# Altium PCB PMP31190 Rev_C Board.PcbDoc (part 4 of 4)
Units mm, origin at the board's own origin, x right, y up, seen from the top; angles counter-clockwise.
Board outline 175.26 x 91.44 mm, 4 copper layers (Top Layer, Mid-Layer 1, Mid-Layer 2, Bottom Layer), stack 1.473 mm thick; 252 components, 140 nets, 735 pads, 501 vias.
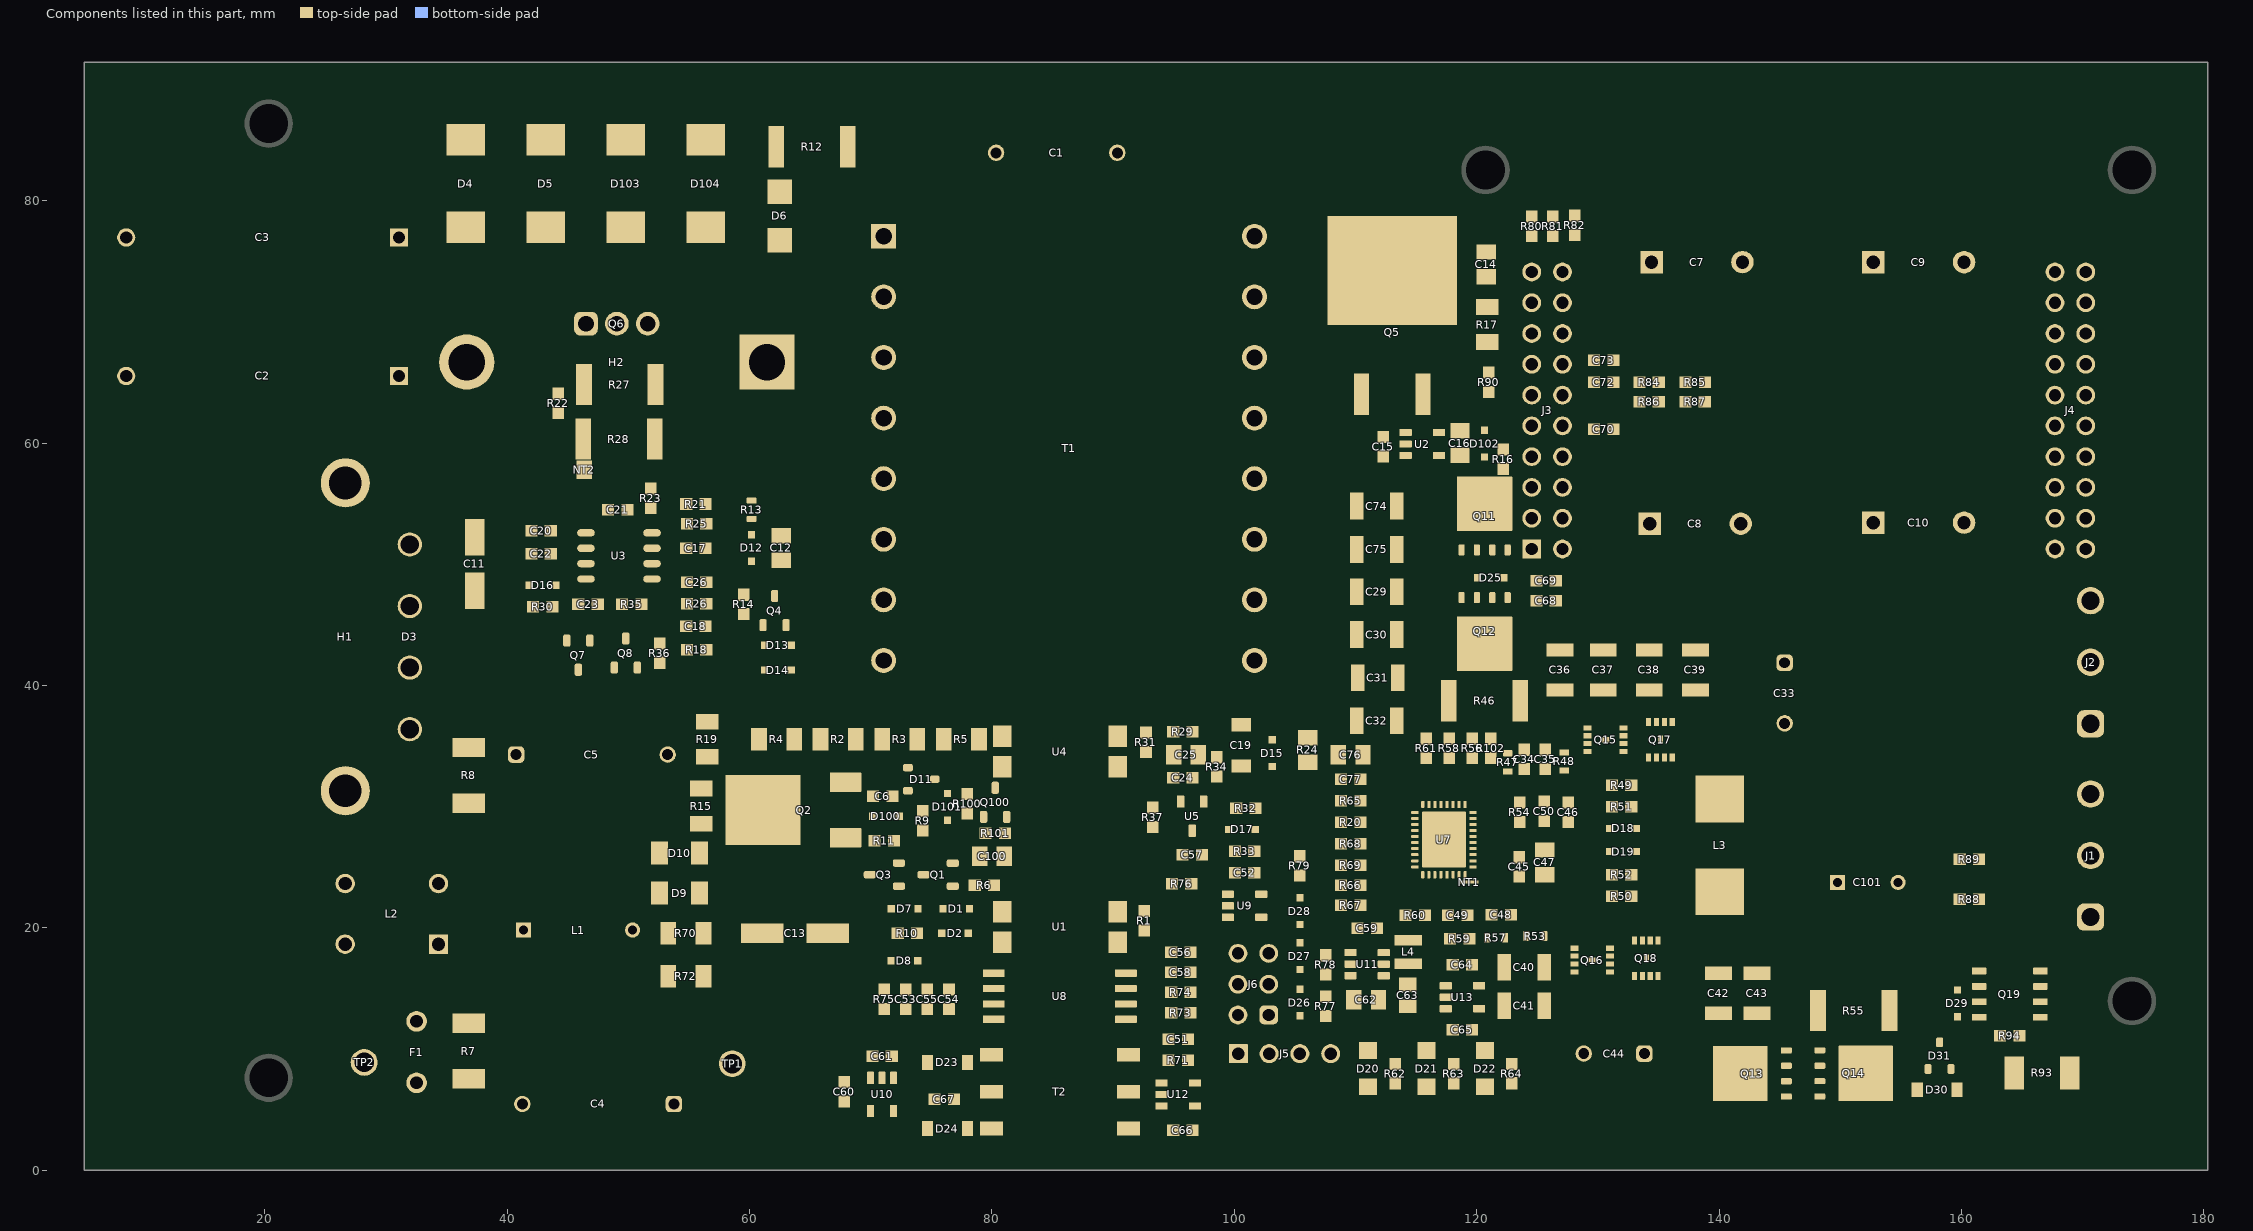
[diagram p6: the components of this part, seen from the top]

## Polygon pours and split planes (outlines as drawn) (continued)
NetD103_1 on Top Layer "TOP_LAYER_NETD103_1_P134" (solid, remove dead copper, pour order 134): 46.863,83.947 48.133,82.677 59.563,82.677 60.452,83.566 60.452,88.011 58.928,89.535 48.133,89.535 46.863,88.265
NetD5_1 on Top Layer "TOP_LAYER_NETD5_1_P130" (solid, remove dead copper, pour order 130): 41.106,80.01 51.435,80.01 52.324,79.121 52.324,73.279 51.435,72.39 45.466,72.39 44.069,70.993 41.275,70.993 40.259,72.009 40.259,79.375
NetD4_1 on Top Layer "TOP_LAYER_NETD4_1_P127" (solid, remove dead copper, pour order 127): 44.831,82.931 45.847,83.947 45.847,88.392 44.831,89.408 25.654,89.408 24.892,88.646 24.892,83.82 25.781,82.931
AGND on Top Layer "TOP_LAYER_AGND_P119" (solid, pour order 119): 106.426,35.433 114.681,35.433 115.316,36.068 125.349,36.068 126.111,35.306 126.111,32.004 125.857,31.75 123.317,31.75 121.793,30.226 116.205,30.226 115.57,29.591 116.332,28.829 116.332,24.638 116.967,24.003 121.336,24.003 122.225,23.114 122.936,23.114 123.571,22.479 125.73,22.479 125.857,22.352 125.857,20.447 125.349,19.939 107.442,19.939 106.426,20.955
NetJ2_1 on Top Layer "TOP_LAYER_NETJ2_1_P091" (solid, pour order 91): 165.695,16.978 166.243,17.526 169.164,17.526 169.926,16.764 169.926,12.065 169.418,11.557 166.37,11.557 165.695,12.232
SGND on Top Layer "TOP_LAYER_SGND_P121" (solid, pour order 121): 104.775,57.785 121.92,57.785 123.19,59.055 123.19,77.47 129.54,83.82 165.1,83.82 176.53,72.39 176.53,22.225 173.355,19.05 170.18,19.05 168.275,17.145 168.275,10.16 160.528,2.413 92.837,2.413 89.535,5.715 89.535,54.61 92.71,57.785
BAT on Top Layer "TOP_LAYER_BAT_P089" (solid, pour order 89): 153.162,14.986 153.924,15.748 158.75,15.748 160.655,17.653 163.195,17.653 163.83,17.018 163.83,13.335 163.576,13.081 159.385,13.081 157.734,11.43 153.416,11.43 153.162,11.684
BAT_SRC on Top Layer "TOP_LAYER_BAT_SRC_P077" (solid, pour order 77): 144.907,9.144 146.558,9.144 147.955,10.541 149.098,10.541 149.225,10.414 149.225,5.715 148.844,5.334 145.161,5.334 144.653,5.842 144.653,9.017
NetC40_1 on Top Layer "TOP_LAYER_NETC40_1_P112" (solid, pour order 112): 138.43,13.589 139.446,14.605 144.526,14.605 145.288,15.367 149.225,15.367 149.86,14.732 149.86,11.303 149.733,11.176 144.78,11.176 144.399,10.795 144.399,5.461 144.018,5.08 131.953,5.08 130.683,6.35 130.683,10.287 129.794,11.176 124.333,11.176 123.952,11.557 123.952,18.034 124.333,18.415 126.238,18.415 127.254,19.431 130.175,19.431 130.429,19.177 130.429,14.859 132.588,12.7 137.541,12.7
NetC45_1 on Top Layer "TOP_LAYER_NETC45_1_P092" (solid, pour order 92): 136.144,25.527 136.652,26.035 141.986,26.035 142.621,25.4 142.621,20.574 141.605,19.558 137.033,19.558 136.398,18.923 136.398,17.272 136.017,16.891 132.461,16.891 131.699,16.129 130.556,16.129 130.556,17.907 131.445,17.907 131.699,18.161 131.699,20.193 132.715,21.209 134.366,21.209 136.144,22.987
NetC46_1 on Top Layer "TOP_LAYER_NETC46_1_P079" (solid, pour order 79): 131.572,36.068 131.826,36.322 139.319,36.322 142.621,33.02 142.621,28.321 142.113,27.813 136.779,27.813 136.144,28.448 136.144,32.639 135.509,33.274 131.826,33.274 131.572,33.528
SYSTEM on Top Layer "TOP_LAYER_SYSTEM_P082" (solid, pour order 82): 122.174,39.751 122.682,40.259 123.571,40.259 124.206,40.894 140.716,40.894 143.383,43.561 145.923,43.561 147.066,42.418 147.066,39.497 146.431,38.862 143.637,38.862 131.699,38.862 131.191,38.354 131.191,34.036 131.064,33.909 126.492,33.909 126.365,34.036 126.365,35.306 125.73,35.941 122.428,35.941 122.174,36.195 122.174,36.322
SGND on Top Layer "TOP_LAYER_SGND_P123" (solid, pour order 123): 120.015,75.184 119.634,75.565 119.634,78.613 119.888,78.867 121.539,78.867 121.793,78.613 121.793,75.184
NetQ12_5 on Top Layer "TOP_LAYER_NETQ12_5_P075" (solid, pour order 75): 123.317,46.101 123.571,45.847 123.571,41.021 123.19,40.64 122.047,40.64 121.92,40.513 121.92,36.957 121.158,36.195 116.84,36.195 116.713,36.322 116.713,40.64 117.729,41.656 117.729,45.593 118.237,46.101 118.491,46.101 118.237,46.101 118.491,46.101
NetD25_2 on Top Layer "TOP_LAYER_NETD25_2_P071" (solid, pour order 71): 118.11,51.689 121.666,51.689 121.793,51.562 121.793,50.165 121.412,49.784 121.412,48.387 121.666,48.133 122.809,48.133 123.063,47.879 123.063,46.609 118.237,46.609 118.11,46.736
+24V on Top Layer "TOP_LAYER_+24V_P076" (solid, pour order 76): 112.395,36.195 111.506,35.306 109.982,35.306 109.728,35.052 109.728,31.877 109.855,31.75 111.252,31.75 112.522,33.02 112.522,33.782 116.205,37.465 116.205,40.64 117.475,41.91 117.475,51.435 118.11,52.07 123.19,52.07 123.19,56.515 121.92,57.785 113.03,57.785 113.03,56.515 112.395,55.88
+24V on Top Layer "TOP_LAYER_+24V_P120" (solid, pour order 120): 147.828,41.656 149.352,40.132 155.702,40.132 156.845,41.275 156.845,79.375 154.94,81.28 133.35,81.28 131.445,79.375 131.445,72.39 135.255,68.58 137.795,68.58 140.335,66.04 140.335,62.23 137.795,59.69 133.985,59.69 132.08,57.785 132.08,48.26 135.255,45.085 145.796,45.085 147.828,43.053
SGND on Top Layer "TOP_LAYER_SGND_P118" (solid, pour order 118): 112.014,66.802 119.38,66.802 119.38,63.5 118.999,63.119 117.983,62.103 117.983,61.722 117.729,61.468 114.935,61.468 113.792,62.611 112.014,62.611
NetQ5_4 on Top Layer "TOP_LAYER_NETQ5_4_P117" (solid, pour order 117): 97.155,83.82 114.3,83.82 115.57,82.55 115.57,80.645 116.84,79.375 118.11,79.375 118.745,78.74 118.745,67.945 118.11,67.31 108.585,67.31 107.315,66.04 107.315,60.325 106.68,59.69 98.425,59.69 97.155,60.96
PGND on Top Layer "TOP_LAYER_PGND_P116" (solid, pour order 116): 45.72,66.675 49.53,66.675 49.53,57.785 45.72,57.785
CGND on Top Layer "TOP_LAYER_CGND_P115" (solid, pour order 115): 81.534,39.751 81.534,6.223 77.724,2.413 66.675,2.413 64.77,4.318 64.77,11.43 60.325,15.875 60.325,38.735 41.275,38.735 34.925,45.085 34.925,55.88 36.83,57.785 64.77,57.785 66.675,55.88 66.675,51.435 69.215,48.895 72.39,48.895
NetQ6_2 on Top Layer "TOP_LAYER_NETQ6_2_P113" (solid, pour order 113): 63.754,71.755 63.754,84.582 65.532,86.36 69.088,86.36 69.088,71.755
NetQ6_3 on Top Layer "TOP_LAYER_NETQ6_3_P111" (solid, pour order 111): 50.165,71.12 50.8,71.755 52.705,71.755 53.975,70.485 53.975,59.055 53.34,58.42 50.165,58.42 50.165,67.31
NetC2_1 on Top Layer "TOP_LAYER_NETC2_1_P101" (solid, pour order 101): 38.989,79.248 38.227,80.01 25.781,80.01 24.765,78.994 24.765,72.136 25.781,71.12 38.227,71.12 38.989,71.882
NetD3_3 on Top Layer "TOP_LAYER_NETD3_3_P094" (solid, pour order 94): 35.38,34.11 35.38,37.26 38.28,37.26 38.28,34.11
NetF1_1 on Top Layer "TOP_LAYER_NETF1_1_P083" (solid, pour order 83): 24.295,20.36 24.75,20.815 27.905,20.815 29.08,19.64 29.21,19.64 30.52,18.33 30.52,15.61 32.137,13.993 33.355,13.993 33.909,13.439 33.909,10.932 33.307,10.33 32.862,10.33 32.849,10.344 30.296,10.344 29.21,11.43 25.712,11.43 24.295,12.847
NetD6_1 on Mid-Layer 2 "MID-LAYER_2_NETD6_1_P135" (solid, remove dead copper, pour order 135): 53.467,79.121 53.467,71.755 54.864,70.358 61.595,70.358 63.5,72.263 63.5,77.978 62.357,79.121 61.214,79.121 60.198,80.137 54.483,80.137
NetD103_1 on Mid-Layer 2 "MID-LAYER_2_NETD103_1_P132" (solid, remove dead copper, pour order 132): 46.863,83.947 48.133,82.677 59.563,82.677 60.452,83.566 60.452,88.011 58.928,89.535 48.133,89.535 46.863,88.265
NetD5_1 on Mid-Layer 2 "MID-LAYER_2_NETD5_1_P128" (solid, remove dead copper, pour order 128): 41.106,80.01 51.435,80.01 52.324,79.121 52.324,73.279 51.435,72.39 45.466,72.39 44.069,70.993 41.275,70.993 40.259,72.009 40.259,79.375
NetC2_1 on Mid-Layer 2 "MID-LAYER_2_NETC2_1_P125" (solid, pour order 125): 38.989,79.248 38.227,80.01 25.781,80.01 24.765,78.994 24.765,72.136 25.781,71.12 38.227,71.12 38.989,71.882
NetJ2_1 on Mid-Layer 2 "MID-LAYER_2_NETJ2_1_P122" (solid, pour order 122): 165.735,37.211 167.259,38.735 172.466,38.735 173.99,37.211 173.99,29.591 172.593,28.194 169.545,28.194 168.91,27.559 168.91,17.907 169.926,16.891 169.926,11.938 169.545,11.557 166.243,11.557 165.735,12.065 165.735,12.319
NetC45_1 on Mid-Layer 2 "MID-LAYER_2_NETC45_1_P074" (solid, pour order 74): 132.588,19.431 135.382,19.431 135.382,16.637 132.588,16.637
NetC40_1 on Mid-Layer 2 "MID-LAYER_2_NETC40_1_P073" (solid, pour order 73): 127.508,18.669 130.302,18.669 130.302,15.875 127.508,15.875
NetC46_1 on Mid-Layer 2 "MID-LAYER_2_NETC46_1_P072" (solid, pour order 72): 133.731,36.322 136.525,36.322 136.525,33.528 133.731,33.528
SYSTEM on Mid-Layer 2 "MID-LAYER_2_SYSTEM_P070" (solid, pour order 70): 128.397,36.957 131.191,36.957 131.191,34.163 128.397,34.163
NetQ5_4 on Mid-Layer 2 "MID-LAYER_2_NETQ5_4_P099" (solid, pour order 99): 97.155,83.82 114.3,83.82 115.57,82.55 115.57,80.645 116.84,79.375 118.11,79.375 118.745,78.74 118.745,67.945 118.11,67.31 108.585,67.31 107.315,66.04 107.315,60.325 106.68,59.69 98.425,59.69 97.155,60.96
NetC2_1 on Mid-Layer 2 "MID-LAYER_2_NETC2_1_P085" (solid, pour order 85): 33.409,49.859 30.182,49.859 29.389,50.652 29.389,60.781 28.295,61.874 27.795,61.874 27.795,77.91 29.895,80.01 34.29,80.01 34.29,75.557 33.655,74.922 33.655,71.12 32.385,69.85 32.385,66.04 33.509,64.916 33.509,50.049
NetD3_2 on Mid-Layer 2 "MID-LAYER_2_NETD3_2_P105" (solid, pour order 105): 29.865,48.09 30.606,48.831 35.23,48.831 52.07,31.991 52.07,19.05 51.435,18.415 48.26,18.415 46.355,20.32 46.355,33.081 42.401,37.035 41.195,37.035 33.509,44.721 30.52,44.721 29.874,45.367 29.865,45.359
NetC5_1 on Mid-Layer 2 "MID-LAYER_2_NETC5_1_P107" (solid, pour order 107): 32.93,22.225 32.975,22.225 33.542,21.658 35.402,21.658 39.28,17.78 39.375,17.685 42.45,17.685 43.815,19.05 43.815,20.955 42.545,22.225 40.257,22.225 38.86,23.622 38.86,26.602 43.165,30.907 43.165,34.619 42.099,35.685 40.065,35.685 39.49,35.11 39.49,30.69 32.93,24.13
NetD3_3 on Mid-Layer 2 "MID-LAYER_2_NETD3_3_P108" (solid, pour order 108): 25.13,22.225 24.495,22.86 24.495,26.348 25.003,26.856 28.106,26.856 34.33,33.08 34.33,37.795 32.755,39.37 30.5,39.37 29.865,40.005 29.865,42.998 30.52,43.653 33.167,43.653 38.28,38.54 38.28,31.182 38.154,31.182 28.63,21.658 25.697,21.658
SGND on Mid-Layer 1 "MID-LAYER_1_SGND_P138" (solid, remove dead copper, pour order 138): 89.662,55.245 89.662,85.09 91.313,86.741 94.361,86.741 95.631,85.471 95.631,55.245
NetD103_1 on Mid-Layer 1 "MID-LAYER_1_NETD103_1_P131" (solid, remove dead copper, pour order 131): 46.863,83.947 48.133,82.677 59.563,82.677 60.452,83.566 60.452,88.011 58.928,89.535 48.133,89.535 46.863,88.265
NetD4_1 on Mid-Layer 1 "MID-LAYER_1_NETD4_1_P126" (solid, remove dead copper, pour order 126): 44.831,82.931 45.847,83.947 45.847,88.392 44.831,89.408 25.654,89.408 24.892,88.646 24.892,83.82 25.781,82.931
NetC2_1 on Mid-Layer 1 "MID-LAYER_1_NETC2_1_P124" (solid, pour order 124): 38.989,79.248 38.227,80.01 25.781,80.01 24.765,78.994 24.765,72.136 25.781,71.12 38.227,71.12 38.989,71.882
AGND on Mid-Layer 1 "MID-LAYER_1_AGND_P109" (solid, pour order 109): 106.426,35.433 114.681,35.433 115.316,36.068 125.349,36.068 126.111,35.306 126.111,32.004 125.857,31.75 123.317,31.75 121.793,30.226 116.205,30.226 115.57,29.591 116.332,28.829 116.332,24.638 116.967,24.003 119.126,24.003 120.015,23.114 122.936,23.114 123.571,22.479 125.679,22.479 125.857,22.301 125.857,20.396 125.4,19.939 107.442,19.939 106.426,20.955
NetC45_1 on Mid-Layer 1 "MID-LAYER_1_NETC45_1_P078" (solid, pour order 78): 132.588,19.431 135.382,19.431 135.382,16.637 132.588,16.637
SGND on Mid-Layer 1 "MID-LAYER_1_SGND_P110" (solid, pour order 110): 89.662,6.223 93.345,2.54 169.545,2.54 176.53,9.525 176.53,78.74 175.895,79.375 171.45,79.375 169.545,81.28 169.545,83.82 168.91,84.455 125.095,84.455 124.46,83.82 124.46,80.645 122.555,78.74 120.65,78.74 120.015,78.105 120.015,67.31 119.507,66.802 109.347,66.802 108.585,66.04 108.585,59.69 107.315,58.42 90.17,58.42 89.662,57.912
NetC45_1 on Mid-Layer 1 "MID-LAYER_1_NETC45_1_P097" (solid, pour order 97): 132.588,19.558 135.382,19.558 135.382,16.764 132.588,16.764
NetC40_1 on Mid-Layer 1 "MID-LAYER_1_NETC40_1_P087" (solid, pour order 87): 127.508,18.796 130.302,18.796 130.302,16.002 127.508,16.002
NetC46_1 on Mid-Layer 1 "MID-LAYER_1_NETC46_1_P080" (solid, pour order 80): 133.731,36.322 136.525,36.322 136.525,33.528 133.731,33.528
SYSTEM on Mid-Layer 1 "MID-LAYER_1_SYSTEM_P084" (solid, pour order 84): 128.524,36.957 131.318,36.957 131.318,34.163 128.524,34.163
NetQ5_4 on Mid-Layer 1 "MID-LAYER_1_NETQ5_4_P106" (solid, pour order 106): 97.155,83.82 114.3,83.82 115.57,82.55 115.57,80.645 116.84,79.375 118.11,79.375 118.745,78.74 118.745,67.945 118.11,67.31 108.585,67.31 107.315,66.04 107.315,60.325 106.68,59.69 98.425,59.69 97.155,60.96
CGND on Mid-Layer 1 "MID-LAYER_1_CGND_P114" (solid, pour order 114): 66.675,55.88 66.675,51.435 69.215,48.895 72.39,48.895 81.534,39.751 81.534,6.223 77.724,2.413 66.802,2.413 64.77,4.445 64.77,11.43 60.325,15.875 60.325,38.672 41.338,38.672 34.989,45.021 34.989,55.245 34.925,55.88 36.83,57.785 49.022,57.785 49.022,57.721 64.834,57.721
NetC2_1 on Mid-Layer 1 "MID-LAYER_1_NETC2_1_P103" (solid, pour order 103): 65.405,69.85 64.77,70.485 56.515,70.485 54.61,72.39 40.005,72.39 38.735,71.12 28.575,71.12 27.94,71.755 27.94,78.105 31.115,81.28 71.755,81.28 74.295,78.74 74.295,71.12 73.025,69.85

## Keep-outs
Keep-Out Layer:
  text ".Layer_Name" at 14.275,-23.427 h1.52

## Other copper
Top Layer:
  text ".Layer_Name" at 14.275,-23.427 h1.52
Bottom Layer:
  text ".Layer_Name" at 14.275,-23.427 h1.52

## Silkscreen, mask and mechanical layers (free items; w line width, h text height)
Top Overlay:
  circle w0.254: c120.769,82.945 r3.582
  circle w0.254: c20.439,7.634 r3.582
  circle w0.254: c20.32,86.36 r3.582
  circle w0.254: c173.981,14.366 r3.582
  circle w0.254: c174.109,82.945 r3.582
  lines w0.254: 17.595,84.034 22.618,88.9 ; 17.714,5.308 22.737,10.174 ; 18.263,83.427 23.309,88.334 ; 18.382,4.701 23.428,9.608 ; 118.044,80.619 123.067,85.485 ; 118.712,80.012 123.758,84.919 ; 171.256,12.04 176.279,16.906 ; 171.384,80.619 176.407,85.485 ; 171.924,11.433 176.97,16.34 ; 172.052,80.012 177.098,84.919
  text "GND" at 178.054,45.974 h1.02 r90
  text "TS" at 177.927,41.275 h1.02 r90
  text "BATT+" at 178.054,34.29 h1.02 r90
  text "SYSTEM+" at 178.054,26.035 h1.02 r90
  text "GND" at 177.927,19.685 h1.02 r90
  text "'.PRJ_Number' .PCB_Rev" at 13.643,18.107 h2 r90
  text "LINE" at 26.416,5.715 h1.02
  text "NTRL" at 57.023,5.588 h1.02
  text ".Layer_Name" at 14.275,-23.427 h1.52
Bottom Overlay:
  lines w0.254: 118.186,11.42 118.186,36.82 cw(c122.801,36.82) 118.948,39.36 ccw(c115.096,41.9) 118.948,44.44 cw(c122.801,46.98) 118.186,46.98 118.186,85.08 176.606,85.08 176.606,46.98 cw(c171.992,46.98) 175.844,44.44 ccw(c179.697,41.9) 175.844,39.36 cw(c171.992,36.82) 176.606,36.82 176.606,11.42 169.875,11.42 cw(c169.875,16.035) 167.335,12.182 ccw(c164.795,8.33) 162.255,12.182 cw(c159.715,16.035) 159.715,11.42 133.807,11.42 133.807,12.436 132.461,12.436 132.461,13.96 131.521,13.96 131.521,12.436 127.711,12.436 127.711,13.96 126.771,13.96 126.771,12.436 125.425,12.436 125.425,11.42
  text ".Layer_Name" at 14.275,-23.427 h1.52
Top Paste:
  text ".Layer_Name" at 14.275,-23.427 h1.52
Bottom Paste:
  text ".Layer_Name" at 14.275,-23.427 h1.52
Top Solder:
  text ".Layer_Name" at 14.275,-23.427 h1.52
  text ".Layer_Name" at 14.275,-23.427 h1.52
Bottom Solder:
  lines w0.254: 118.186,11.42 125.425,11.42
  text "'.PRJ_Number' .PCB_Rev" at 13.568,55.478 h2 r90
  text ".Layer_Name" at 14.275,-23.427 h1.52
Drill Guide:
  text ".Layer_Name" at 14.275,-23.427 h1.52
M1 Board Outline:
  the board outline again, w0.8
  text ".Layer_Name" at 14.275,-23.427 h1.52
M2 Board Dimensions:
  rectangle: -0.381,-8.606 2.794,-5.431
  rectangle: 2.794,-11.781 12.319,-8.606
  lines w0.178: -0.381,-8.606 25.019,-8.606 ; 2.794,-11.781 2.794,-5.431 ; 5.969,-11.781 5.969,-5.431 ; 12.319,-11.781 12.319,-5.431 ; 18.669,-11.781 18.669,-5.431 ; -0.381,-11.781 25.019,-11.781 25.019,-5.431 -0.381,-5.431 -0.381,-11.781
  text "'.Print_Date' '.Print_Time'" at 2.794,105.061 h2
  text ".Layer_Name" at 14.275,-23.427 h1.52
M3 3D STEP Top:
  text ".Layer_Name" at 14.275,-23.427 h1.52
M4 3D STEP Bottom:
  text ".Layer_Name" at 14.275,-23.427 h1.52
M5 Assembly Top:
  lines w0.254: -7.798,-25.248 159.842,-25.248 ; -7.798,-20.083 159.893,-20.083 ; -7.798,-14.918 -7.798,-30.412 93.929,-30.412 159.893,-30.412 159.893,-14.918 -7.785,-14.918 -7.785,-30.412 32.233,-30.412 ; 24.765,45.72 26.645,45.72 ; 28.33,45.72 30.946,45.72 ; 54.813,-30.412 54.813,-14.918 ; 86.995,-20.083 86.995,-14.918 ; 108.331,-20.083 108.331,-14.918 ; 124.13,-30.577 124.13,-25.425
  text "COMPONENTS MARKED 'DNP' SHOULD NOT BE POPULATED." at 28.918,-9.711 h1.52
  text "ASSEMBLY VARIANT:" at 28.905,-12.645 h1.52
  text ".VariantName" at 55.22,-12.645 h1.52
  text "PCB VIEWED FROM TOP SIDE" at -6.185,-18.275 h1.52
  text "BOARD #:" at 56.718,-18.275 h1.52
  text ".PRJ_Number" at 70.574,-18.275 h1.52
  text "REV:" at 92.024,-18.275 h1.52
  text ".PCB_Rev" at 99.428,-18.275 h1.52
  text "SVN REV:" at 113.309,-18.275 h1.52
  text ".VersionControl_RevNumber" at 126.162,-18.275 h1.52
  text "TID #:" at 56.718,-23.44 h1.52
  text ".TID" at 70.574,-23.44 h1.52
  text "PLOT NAME =" at -6.185,-28.655 h1.52
  text ".plot_File_Name" at 14.275,-28.655 h1.52
  text "GENERATED    :" at 56.769,-28.655 h1.52
  text ".Print_Date" at 78.854,-28.655 h1.52
  text ".Print_Time" at 97.371,-28.655 h1.52
  text "TEXAS INSTRUMENTS" at 129.489,-28.655 h1.52
M6 Assembly Bottom:
  lines w0.254: -7.81,-20.096 159.88,-20.096 ; -7.76,-25.26 159.88,-25.26 ; 27.953,-30.59 27.953,-25.438 ; 43.752,-20.096 43.752,-14.931 ; 65.087,-20.096 65.087,-14.931 ; 97.269,-30.425 97.269,-14.931 ; 119.85,-30.425 159.868,-30.425 159.868,-14.931 -7.81,-14.931 -7.81,-30.425 58.153,-30.425 159.88,-30.425 159.88,-14.931
  text "COMPONENTS MARKED 'DNP' SHOULD NOT BE POPULATED." at 154.61,-9.699 h1.52
  text ".VariantName" at 128.092,-12.645 h1.52
  text "ASSEMBLY VARIANT:" at 154.483,-12.645 h1.52
  text ".VersionControl_RevNumber" at 25.921,-18.288 h1.52
  text "SVN REV:" at 38.773,-18.288 h1.52
  text ".PCB_Rev" at 52.654,-18.288 h1.52
  text "REV:" at 60.058,-18.288 h1.52
  text ".PRJ_Number" at 81.509,-18.288 h1.52
  text "BOARD #:" at 95.364,-18.288 h1.52
  text "PCB VIEWED FROM BOTTOM SIDE" at 158.267,-18.288 h1.52
  text ".TID" at 81.509,-23.453 h1.52
  text "TID #:" at 95.364,-23.453 h1.52
  text "TEXAS INSTRUMENTS" at 22.593,-28.668 h1.52
  text ".Print_Time" at 54.712,-28.668 h1.52
  text ".Print_Date" at 73.228,-28.668 h1.52
  text "GENERATED    :" at 95.313,-28.668 h1.52
  text ".plot_File_Name" at 137.808,-28.668 h1.52
  text "PLOT NAME =" at 158.267,-28.668 h1.52
M9 Title Sheet:
  drawing of 57 lines, arcs and shapes, not listed
  text "1" at 18.411,202.506 h1.78
  text "2" at 81.801,202.506 h1.78
  text "3" at 145.03,202.506 h1.78
  text "4" at 208.699,202.506 h1.78
  text "5" at 272.174,202.506 h1.78
  text "6" at 335.801,202.506 h1.78
  text "A" at -10.96,173.474 h1.78
  text "A" at 364.96,173.474 h1.78
  text "B" at -10.96,113.022 h1.78
  text "B" at 364.96,113.022 h1.78
  text "C" at -10.96,52.697 h1.78
  text "C" at 364.96,52.697 h1.78
  text "PROJECT TITLE:" at 287.744,5.427 h1.14
  text ".PRJ_Title" at 289.014,2.041 h1.78
  text "DESIGNED FOR:" at 287.744,-2.218 h1.14
  text ".PRJ_Customer" at 289.014,-5.774 h1.78
  text "D" at -10.96,-7.501 h1.78
  text "D" at 364.96,-7.501 h1.78
  text "FILE NAME:" at 287.744,-9.838 h1.14
  text ".PCB_File_Name_No_Path" at 289.014,-12.886 h1.78
  text "Texas Instruments (TI) and/or its licensors do not warrant the accuracy or completeness of this specification" at 161.519,-16.997 h1.14
  text "ENGINEER:" at 287.744,-17.204 h1.14
  text "LAYOUT BY:" at 325.971,-17.204 h1.14
  text "or any information contained therein. TI and/or its licensors do not warrant that this design will meet" at 160.376,-19.859 h1.14
  text ".PRJ_Engineer" at 289.014,-21.141 h1.78
  text ".PCB_Layout" at 327.254,-21.141 h1.78
  text "the specifications, will be suitable for your application or fit for any particular purpose, or will operate in" at 160.376,-22.72 h1.14
  text ".Layer_Name" at 14.275,-23.427 h1.52
  text "ALTIUM DESIGNER VERSION:" at 325.971,-25.078 h1.14
  text "an implementation. TI and/or its licensors do not warrant that the design is production worthy. You should" at 160.376,-25.582 h1.14
  text "completely validate and test your design implementation to confirm the system functionality for your application." at 161.519,-28.444 h1.14
  text ".print_Scale" at 289.014,-28.465 h1.78
  text ".Application_BuildNumber" at 327.254,-28.465 h1.78
  text "1" at 18.411,-33.714 h1.78
  text "2" at 81.801,-33.714 h1.78
  text "3" at 145.03,-33.714 h1.78
  text "4" at 208.699,-33.714 h1.78
  text "5" at 272.174,-33.714 h1.78
  text "6" at 335.801,-33.714 h1.78
M10 Fab Notes:
  drawing of 189 lines, arcs and shapes, not listed
  text "DESIGN INFORMATION" at 314.122,159.826 h1.52
  text "MIN. TRACK WIDTH:" at 297.75,156.469 h1.52
  text "8" at 325.595,156.47 h1.52
  text "MIL" at 329.526,156.469 h1.52
  text "MIN. CLEARANCE:" at 297.75,153.317 h1.52
  text "0.2" at 324.071,153.317 h1.52
  text "mm" at 329.526,153.317 h1.52
  text "MIN. VIA PAD SIZE:" at 297.75,150.164 h1.52
  text "24" at 324.833,150.164 h1.52
  text "MIL" at 329.526,150.164 h1.52
  text "0.05mm (2MIL)" at 315.403,146.864 h1.52
  text "MINIMUM ANNULAR RING" at 289.388,146.656 h1.52
  text "EXTERNAL" at 333.387,146.656 h1.52
  text "PER" at 294.468,143.858 h1.52
  text "IPC-D-275 CLASS 2 LEVEL C" at 300.056,143.858 h1.52
  text "MIL, HOLES" at 337.857,141.306 h1.52
  text "+/-" at 327.889,141.088 h1.52
  text "+/-" at 349.58,141.088 h1.52
  text "REGISTRATION TOLERANCES:" at 289.388,141.061 h1.52
  text "METAL" at 319.862,141.061 h1.52
  text "5" at 334.498,141.061 h1.52
  text "3" at 355.656,141.061 h1.52
  text "MIL" at 358.609,141.061 h1.52
  text "HOLE SIZE TOLERANCE (UNLESS OTHERWISE SPECIFIED):" at 289.388,138.564 h1.52
  text "+/-" at 349.58,138.491 h1.52
  text "3" at 355.656,138.464 h1.52
  text "MIL" at 358.609,138.464 h1.52
  text "MATERIAL:" at 287.489,134.968 h1.52
  text "FR-4 High Tg" at 312.545,131.703 h1.52
  text "X" at 308.876,131.5 h1.52
  text "FR-408" at 298.182,131.385 h1.52
  text "OTHER" at 335.977,131.385 h1.52
  text "62 MIL (1.6mm) +/-10%" at 306.313,127.753 h1.52
  text "X" at 303.262,127.69 h1.52
  text "THICKNESS:" at 289.388,127.544 h1.52
  text "OTHER" at 338.949,127.544 h1.52
  text "TOLERANCE:" at 289.388,124.031 h1.52
  text "X" at 310.933,124.031 h1.52
  text "ANSI IPC-6012 TYPE 3 CLASS 2" at 315.455,124.031 h1.52
  text "OTHER +/-" at 315.454,120.368 h1.52
  text "BOW & TWIST:" at 289.388,116.68 h1.52
  text "X" at 310.933,116.68 h1.52
  text "ANSI IPC-6012 TYPE 3 CLASS 2" at 315.455,116.68 h1.52
  text "OTHER +/-" at 315.454,112.954 h1.52
  text "DRILLING:" at 287.489,109.637 h1.52
  text "NC_DRILL FILES" at 332.218,106.965 h1.52
  text "REFERENCE:" at 289.388,106.865 h1.52
  text "X" at 306.082,106.862 h1.52
  text "AS SHOWN" at 310.603,106.865 h1.52
  text "X" at 328.967,106.865 h1.52
  text "OTHER" at 339.787,103.252 h1.52
  text "PTH COPPER THICKNESS:" at 289.38,103.162 h1.52
  text "X" at 318.316,103.162 h1.52
  text "20-30 um" at 321.567,103.162 h1.52
  text "BOARD FINISH:" at 287.489,99.413 h1.52
  text "SILKSCREEN:" at 291.431,96.616 h1.52
  text "X" at 315.759,96.616 h1.52
  text "TOP" at 318.731,96.616 h1.52
  text "X" at 328.713,96.616 h1.52
  text "BOTTOM" at 331.71,96.616 h1.52
  text "SILKSCREEN COLOR:" at 291.431,92.674 h1.52
  text "X" at 315.734,92.674 h1.52
  text "WHITE" at 318.731,92.674 h1.52
  text "OTHER" at 331.71,92.674 h1.52
  text "X" at 319.061,89.03 h1.52
  text "GREEN" at 322.058,89.03 h1.52
  text "OTHER" at 337.755,89.03 h1.52
  text "SOLDER RESIST COLOR:" at 291.431,88.856 h1.52
  text "X" at 319.061,85.112 h1.52
  text "MATTE" at 322.058,85.112 h1.52
  text "SEMI-GLOSS" at 337.744,85.096 h1.52
  text "IMMERSION GOLD (ENIG)" at 314.438,80.724 h1.52
  text "ENEPIG" at 348.412,80.54 h1.52
  text "SURFACE FINISH:" at 287.489,80.515 h1.52
  text "X" at 309.917,80.515 h1.52
  text "IMM. TIN/SILVER OR EQUIV" at 295.859,77.027 h1.52
  text "OTHER" at 332.218,76.927 h1.52
  text "ARRAY/PANEL:" at 287.489,72.981 h1.52
  text "CUT AND TRIM PER M1 BOARD OUTLINE" at 314.438,72.772 h1.52
  text "N.C. ROUTE" at 314.438,69.318 h1.52
  text "X" at 331.914,69.318 h1.52
  text "V. SCORE" at 336.435,69.318 h1.52
  text "CERTIFICATION:" at 287.489,66.038 h1.52
  text "MATERIALS AND WORKMANSHIP FOR ALL PCBS" at 305.904,66.038 h1.52
  text "TO MEET OR EXCEED THE REQUIREMENTS OF:" at 305.904,63.649 h1.52
  text "X" at 296.697,60.382 h1.52
  text "ANSI IPC-A-600F CLASS ->" at 299.948,60.382 h1.52
  text "X" at 341.807,60.382 h1.52
  text "2" at 344.601,60.382 h1.52
  text "1" at 336.6,60.344 h1.52
  text "3" at 353.592,60.344 h1.52
  text "X" at 317.321,56.631 h1.52
  text "RoHS" at 320.572,56.631 h1.52
  text "OTHER" at 336.94,56.631 h1.52
  text "PER ORDER" at 347.026,56.631 h1.52
  text "ALL BOARDS MUST MEET OR EXCEED UL94-V0 REQUIREMENTS." at 288.188,52.724 h1.52
  text "PCB MUST BEAR THE UL94V-0 UL REGISTERED MATERIAL ID NUMBER" at 288.188,49.776 h1.52
  text "ADDITIONAL REQUIREMENTS:" at 287.489,45.472 h1.52
  text "MICROSECTION:" at 289.388,42.751 h1.52
  text "YES" at 312.394,42.751 h1.52
  text "REQUIRED" at 334.276,39.085 h1.52
  text "BARE BOARD ELEC. TEST:" at 289.388,39.013 h1.52
  text "NONE" at 322.554,39.013 h1.52
  text "X" at 331.279,39.013 h1.52
  text "PER ORDER" at 349.312,39.013 h1.52
  text "XX MIL VIAS REQUIRE NON-CONDUCTIVE FILL AND PLANARIZE" at 293.659,33.807 h1.5
  text "XX MIL VIAS REQUIRE CONDUCTIVE FILL AND PLANARIZE" at 293.862,31.166 h1.52
  text "OUTER XX MIL TRACES REQUIRE 50 OHM SINGLE-ENDED IMPEDANCE" at 293.837,27.016 h1.47
  text "LAYER 2 & 3 (INNER LAYERS) XX MIL WIDE, XX MIL SPACE / TRACES REQUIRE 100 OHM DIFFERENTIAL IMPEDANCE" at 293.634,21.029 h1.52
  text ".Layer_Name" at 14.275,-23.427 h1.52
M11 Gerber Information:
  lines w0.254: -7.798,-25.248 159.842,-25.248 ; -7.798,-20.083 159.893,-20.083 ; -7.798,-14.918 -7.798,-30.412 93.929,-30.412 159.893,-30.412 159.893,-14.918 -7.785,-14.918 -7.785,-30.412 32.233,-30.412 ; 54.813,-30.412 54.813,-14.918 ; 86.995,-20.083 86.995,-14.918 ; 108.331,-20.083 108.331,-14.918 ; 124.13,-30.577 124.13,-25.425
  text "ALL ARTWORK VIEWED FROM TOP SIDE" at -6.185,-18.275 h1.52
  text "BOARD #:" at 56.718,-18.275 h1.52
  text ".PRJ_Number" at 70.574,-18.275 h1.52
  text "REV:" at 92.024,-18.275 h1.52
  text ".PCB_Rev" at 99.428,-18.275 h1.52
  text "SVN REV:" at 113.309,-18.275 h1.52
  text ".VersionControl_RevNumber" at 126.162,-18.275 h1.52
  text "LAYER NAME =" at -6.185,-23.427 h1.52
  text "TID #:" at 56.718,-23.44 h1.52
  text ".TID" at 70.574,-23.44 h1.52
  text "PLOT NAME =" at -6.185,-28.655 h1.52
  text ".plot_File_Name" at 14.275,-28.655 h1.52
  text "GENERATED    :" at 56.769,-28.655 h1.52
  text ".Print_Date" at 78.854,-28.655 h1.52
  text ".Print_Time" at 97.371,-28.655 h1.52
  text "TEXAS INSTRUMENTS" at 129.489,-28.655 h1.52
M12 Stackup:
  drawing of 295 lines, arcs and shapes, not listed
  text "Layer" at 166.629,192.278 h1.52
  text "Name" at 177.04,192.278 h1.52
  text "Material" at 200.656,192.278 h1.52
  text "Thickness" at 222.494,192.278 h1.52
  text "Constant" at 239,192.278 h1.52
  text "Board Layer Stack" at 253.474,192.278 h1.52
  text "Top Overlay" at 177.04,189.23 h1.52
  text "Top Solder" at 177.04,186.182 h1.52
  text "Solder Resist" at 200.656,186.182 h1.52
  text "0.180mm" at 222.494,186.182 h1.52
  text "3.5" at 239,186.182 h1.52
  text "1" at 166.629,183.134 h1.52
  text "Top Layer" at 177.04,183.134 h1.52
  text "0.070mm" at 222.494,183.134 h1.52
  text "Dielectric1" at 177.04,180.086 h1.52
  text "FR-4" at 200.656,180.086 h1.52
  text "0.232mm" at 222.494,180.086 h1.52
  text "4.8" at 239,180.086 h1.52
  text "2" at 166.629,177.038 h1.52
  text "Mid-Layer 1" at 177.04,177.038 h1.52
  text "0.036mm" at 222.494,177.038 h1.52
  text "Dielectric2" at 177.04,173.99 h1.52
  text "FR-4" at 200.656,173.99 h1.52
  text "0.710mm" at 222.494,173.99 h1.52
  text "4.8" at 239,173.99 h1.52
  text "3" at 166.629,170.942 h1.52
  text "Mid-Layer 2" at 177.04,170.942 h1.52
  text "0.036mm" at 222.494,170.942 h1.52
  text "Dielectric3" at 177.04,167.894 h1.52
  text "FR-4" at 200.656,167.894 h1.52
  text "0.320mm" at 222.494,167.894 h1.52
  text "4.8" at 239,167.894 h1.52
  text "4" at 166.629,164.846 h1.52
  text "Bottom Layer" at 177.04,164.846 h1.52
  text "0.070mm" at 222.494,164.846 h1.52
  text "Bottom Solder" at 177.04,161.798 h1.52
  text "Solder Resist" at 200.656,161.798 h1.52
  text "0.018mm" at 222.494,161.798 h1.52
  text "3.5" at 239,161.798 h1.52
  text "Bottom Overlay" at 177.04,158.75 h1.52
  text ".Layer_Name" at 14.275,-23.427 h1.52
M13 Component Bodies Top:
  text ".Layer_Name" at 14.275,-23.427 h1.52
M14 Component Bodies Bottom:
  text ".Layer_Name" at 14.275,-23.427 h1.52
M15 Courtyards Top:
  text ".Layer_Name" at 14.275,-23.427 h1.52
M16 Courtyards Bottom:
  text ".Layer_Name" at 14.275,-23.427 h1.52
Drill Drawing:
  drawing of 184 lines, arcs and shapes, not listed
  text "Symbol" at 195.239,148.162 h1.83
  text "Quantity" at 202.874,148.162 h1.83
  text "Finished Hole Size" at 211.306,148.162 h1.83
  text "Plated" at 227.475,148.162 h1.83
  text "Hole Type" at 234.057,148.162 h1.83
  text "Drill Layer Pair" at 243.586,148.162 h1.83
  text "Hole Tolerance" at 261.984,148.162 h1.83
  text "16" at 202.874,145.004 h1.52
  text "7.87mil (0.200mm)" at 211.306,145.004 h1.52
  text "PTH" at 227.475,145.004 h1.52
  text "Round" at 234.057,145.004 h1.52
  text "Top Layer - Bottom Layer" at 243.586,145.004 h1.52
  text "25" at 202.874,141.847 h1.52
  text "11.81mil (0.300mm)" at 211.306,141.847 h1.52
  text "PTH" at 227.475,141.847 h1.52
  text "Round" at 234.057,141.847 h1.52
  text "Top Layer - Bottom Layer" at 243.586,141.847 h1.52
  text "153" at 202.874,138.689 h1.52
  text "12.00mil (0.305mm)" at 211.306,138.689 h1.52
  text "PTH" at 227.475,138.689 h1.52
  text "Round" at 234.057,138.689 h1.52
  text "Top Layer - Bottom Layer" at 243.586,138.689 h1.52
  text "B" at 194.597,138.435 h1.4
  text "157" at 202.874,135.531 h1.52
  text "16.00mil (0.406mm)" at 211.306,135.531 h1.52
  text "PTH" at 227.475,135.531 h1.52
  text "Round" at 234.057,135.531 h1.52
  text "Top Layer - Bottom Layer" at 243.586,135.531 h1.52
  text "38" at 202.874,132.373 h1.52
  text "20.00mil (0.508mm)" at 211.306,132.373 h1.52
  text "PTH" at 227.475,132.373 h1.52
  text "Round" at 234.057,132.373 h1.52
  text "Top Layer - Bottom Layer" at 243.586,132.373 h1.52
  text "A" at 194.597,132.12 h1.4
  text "40" at 202.874,129.216 h1.52
  text "23.62mil (0.600mm)" at 211.306,129.216 h1.52
  text "PTH" at 227.475,129.216 h1.52
  text "Round" at 234.057,129.216 h1.52
  text "Top Layer - Bottom Layer" at 243.586,129.216 h1.52
  text "E" at 194.597,128.962 h1.4
  text "72" at 202.874,126.058 h1.52
  text "28.00mil (0.711mm)" at 211.306,126.058 h1.52
  text "PTH" at 227.475,126.058 h1.52
  text "Round" at 234.057,126.058 h1.52
  text "Top Layer - Bottom Layer" at 243.586,126.058 h1.52
  text "4" at 202.874,122.9 h1.52
  text "29.53mil (0.750mm)" at 211.306,122.9 h1.52
  text "PTH" at 227.475,122.9 h1.52
  text "Round" at 234.057,122.9 h1.52
  text "Top Layer - Bottom Layer" at 243.586,122.9 h1.52
  text "C" at 194.597,122.646 h1.4
  text "10" at 202.874,119.742 h1.52
  text "35.43mil (0.900mm)" at 211.306,119.742 h1.52
  text "PTH" at 227.475,119.742 h1.52
  text "Round" at 234.057,119.742 h1.52
  text "Top Layer - Bottom Layer" at 243.586,119.742 h1.52
  text "4" at 202.874,116.585 h1.52
  text "39.37mil (1.000mm)" at 211.306,116.585 h1.52
  text "PTH" at 227.475,116.585 h1.52
  text "Round" at 234.057,116.585 h1.52
  text "Top Layer - Bottom Layer" at 243.586,116.585 h1.52
  text "D" at 194.597,116.331 h1.4
  text "50" at 202.874,113.427 h1.52
  text "40.16mil (1.020mm)" at 211.306,113.427 h1.52
  text "PTH" at 227.475,113.427 h1.52
  text "Round" at 234.057,113.427 h1.52
  text "Top Layer - Bottom Layer" at 243.586,113.427 h1.52
  text "2" at 202.874,110.269 h1.52
  text "41.34mil (1.050mm)" at 211.306,110.269 h1.52
  text "PTH" at 227.475,110.269 h1.52
  text "Round" at 234.057,110.269 h1.52
  text "Top Layer - Bottom Layer" at 243.586,110.269 h1.52
  text "12" at 202.874,107.112 h1.52
  text "43.31mil (1.100mm)" at 211.306,107.112 h1.52
  text "PTH" at 227.475,107.112 h1.52
  text "Round" at 234.057,107.112 h1.52
  text "Top Layer - Bottom Layer" at 243.586,107.112 h1.52
  text "3" at 202.874,103.954 h1.52
  text "51.18mil (1.300mm)" at 211.306,103.954 h1.52
  text "PTH" at 227.475,103.954 h1.52
  text "Round" at 234.057,103.954 h1.52
  text "Top Layer - Bottom Layer" at 243.586,103.954 h1.52
  text "16" at 202.874,100.796 h1.52
  text "53.15mil (1.350mm)" at 211.306,100.796 h1.52
  text "PTH" at 227.475,100.796 h1.52
  text "Round" at 234.057,100.796 h1.52
  text "Top Layer - Bottom Layer" at 243.586,100.796 h1.52
  text "10" at 202.874,97.638 h1.52
  text "59.06mil (1.500mm)" at 211.306,97.638 h1.52
  text "PTH" at 227.475,97.638 h1.52
  text "Round" at 234.057,97.638 h1.52
  text "Top Layer - Bottom Layer" at 243.586,97.638 h1.52
  text "2" at 202.874,94.481 h1.52
  text "63.00mil (1.600mm)" at 211.306,94.481 h1.52
  text "PTH" at 227.475,94.481 h1.52
  text "Round" at 234.057,94.481 h1.52
  text "Top Layer - Bottom Layer" at 243.586,94.481 h1.52
  text "2" at 202.874,91.323 h1.52
  text "106.30mil (2.700mm)" at 211.306,91.323 h1.52
  text "PTH" at 227.475,91.323 h1.52
  text "Round" at 234.057,91.323 h1.52
  text "Top Layer - Bottom Layer" at 243.586,91.323 h1.52
  text "+/-1.97mil" at 261.984,91.323 h1.52
  text "2" at 202.874,88.165 h1.52
  text "118.11mil (3.000mm)" at 211.306,88.165 h1.52
  text "PTH" at 227.475,88.165 h1.52
  text "Round" at 234.057,88.165 h1.52
  text "Top Layer - Bottom Layer" at 243.586,88.165 h1.52
  text "5" at 202.874,85.007 h1.52
  text "125.98mil (3.200mm)" at 211.306,85.007 h1.52
  text "PTH" at 227.475,85.007 h1.52
  text "Round" at 234.057,85.007 h1.52
  text "Top Layer - Bottom Layer" at 243.586,85.007 h1.52
  text "623 Total" at 202.874,81.85 h1.52
  text ".Layer_Name" at 14.275,-23.427 h1.52
M17 Embedded Cavity:
  text ".Layer_Name" at 14.275,-23.427 h1.52
M18 Embedded Assembly:
  text ".Layer_Name" at 14.275,-23.427 h1.52
M19 Embedded Keepout:
  text ".Layer_Name" at 14.275,-23.427 h1.52

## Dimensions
-0.381,-11.781 to 25.019,-11.781 on M2 Board Dimensions
5.08,91.44 to 5.08,0 on M2 Board Dimensions
5.08,0 to 180.34,0 on M2 Board Dimensions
